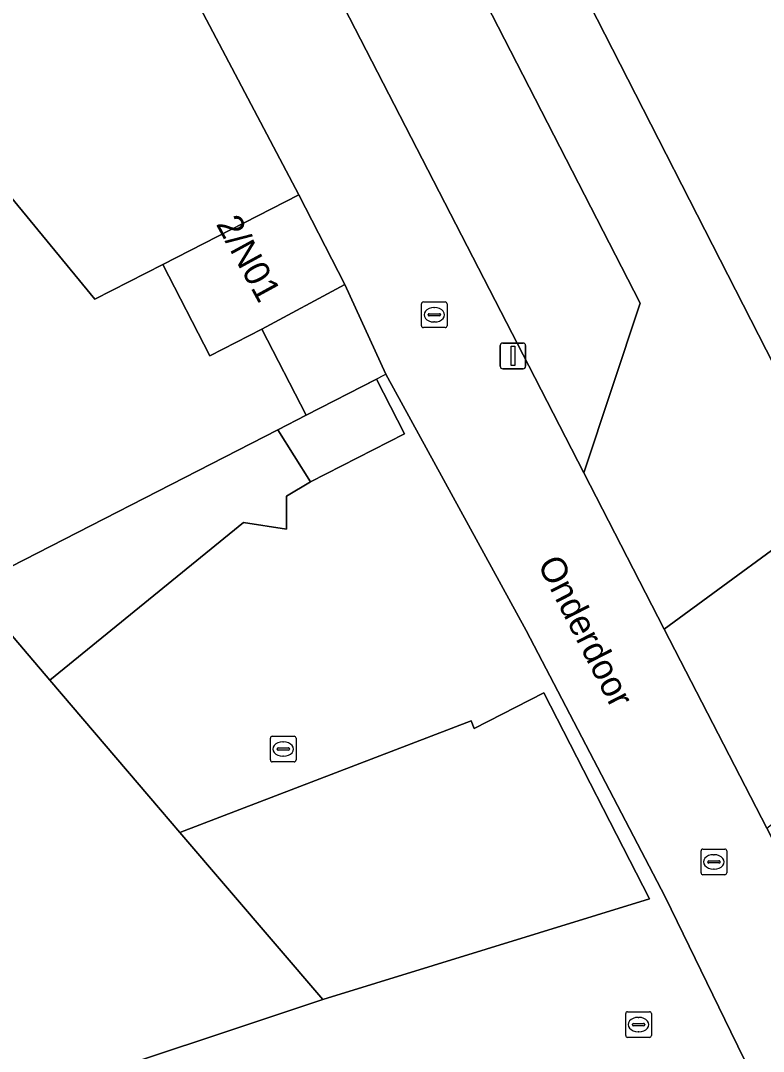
# Model space of a CAD drawing. Extents: x 161087 to 161926, y 382572 to 383873.
# Drawn here: x 161751.28 to 161780.24, y 382874.64 to 382914.81 of the extents above; entities that cross this region are included whole.
import ezdxf

# ---------------------------------------------------------------- set-up
doc = ezdxf.new("R2010")
doc.units = 0
for name, color, linetype in [('IMGEO_Erf', 7, 'Continuous'), ('IMGEO_Hek', 7, 'Continuous'), ('IMGEO_Kolk', 7, 'Continuous'), ('IMGEO_Lichtmast', 7, 'Continuous'), ('IMGEO_Muur', 7, 'Continuous'), ('IMGEO_Openbare_ruimte_label', 7, 'Continuous'), ('IMGEO_Pand', 7, 'Continuous'), ('IMGEO_Pand_nummerreeks', 7, 'Continuous'), ('IMGEO_Parkeervlak_gesloten', 7, 'Continuous'), ('IMGEO_Rijbaan_lokaal_gesloten', 7, 'Continuous'), ('IMGEO_Rijbaan_lokaal_open', 7, 'Continuous')]:
    doc.layers.add(name, color=color, linetype=linetype)

msp = doc.modelspace()

# ---------------------------------------------------------------- linework, layer by layer
at = {"layer": 'IMGEO_Erf'}
msp.add_lwpolyline([(161781.64, 382869.915), (161778.973, 382875.402), (161776.413, 382880.664), (161770.996, 382891.041), (161765.524, 382901.027), (161763.926, 382904.529), (161760.691, 382902.783), (161762.41, 382899.43), (161765.159, 382900.837), (161766.249, 382898.71), (161762.579, 382896.831), (161761.653, 382896.272), (161761.648, 382894.996), (161759.969, 382895.256), (161752.426, 382889.102), (161756.738, 382884.057), (161757.493, 382883.174), (161768.844, 382887.525), (161768.961, 382887.22), (161771.685, 382888.614), (161775.793, 382880.58), (161763.065, 382876.655), (161758.653, 382875.193), (161754.772, 382873.907)], dxfattribs=at)
at = {"layer": 'IMGEO_Hek'}
for points in [[(161771.091, 382901.359), (161773.236, 382897.192), (161776.376, 382891.093), (161780.366, 382883.342), (161784.138, 382876.015)], [(161762.41, 382899.43), (161765.524, 382901.027)], [(161765.524, 382901.027), (161770.996, 382891.041)]]:
    msp.add_lwpolyline(points, dxfattribs=at)
at = {"layer": 'IMGEO_Kolk'}
for p, q in [((161766.909, 382902.921), (161766.909, 382903.773)), ((161766.984, 382903.847), (161767.836, 382903.847)), ((161767.91, 382903.773), (161767.91, 382902.921)), ((161767.168, 382903.341), (161767.168, 382903.353)), ((161767.606, 382903.304), (161767.208, 382903.304)), ((161767.211, 382903.39), (161767.609, 382903.39)), ((161767.397, 382903.627), (161767.422, 382903.627)), ((161767.652, 382903.353), (161767.652, 382903.341)), ((161767.42, 382903.067), (161767.395, 382903.067)), ((161767.836, 382902.847), (161766.984, 382902.847)), ((161761.02, 382885.995), (161761.02, 382886.847)), ((161761.095, 382886.921), (161761.947, 382886.921)), ((161762.021, 382886.847), (161762.021, 382885.995)), ((161761.279, 382886.415), (161761.279, 382886.427)), ((161761.322, 382886.464), (161761.72, 382886.464)), ((161761.508, 382886.701), (161761.533, 382886.701)), ((161761.763, 382886.427), (161761.763, 382886.415)), ((161761.717, 382886.378), (161761.319, 382886.378)), ((161761.531, 382886.141), (161761.506, 382886.141)), ((161761.947, 382885.921), (161761.095, 382885.921)), ((161777.807, 382881.597), (161777.807, 382882.449)), ((161777.882, 382882.523), (161778.734, 382882.523)), ((161778.808, 382882.449), (161778.808, 382881.597)), ((161778.066, 382882.017), (161778.066, 382882.029)), ((161778.109, 382882.066), (161778.507, 382882.066)), ((161778.295, 382882.303), (161778.32, 382882.303)), ((161778.55, 382882.029), (161778.55, 382882.017)), ((161778.504, 382881.98), (161778.106, 382881.98)), ((161778.318, 382881.743), (161778.293, 382881.743)), ((161778.734, 382881.523), (161777.882, 382881.523)), ((161774.87, 382875.256), (161774.87, 382876.108)), ((161774.945, 382876.182), (161775.797, 382876.182)), ((161775.871, 382876.108), (161775.871, 382875.256)), ((161775.129, 382875.676), (161775.129, 382875.688)), ((161775.567, 382875.639), (161775.169, 382875.639)), ((161775.172, 382875.725), (161775.57, 382875.725)), ((161775.358, 382875.962), (161775.383, 382875.962)), ((161775.613, 382875.688), (161775.613, 382875.676)), ((161775.797, 382875.182), (161774.945, 382875.182)), ((161775.381, 382875.402), (161775.356, 382875.402))]:
    msp.add_line(p, q, dxfattribs=at)
for points in [[(161766.909, 382902.921), (161766.909, 382903.773)], [(161766.984, 382903.847), (161767.836, 382903.847)], [(161767.91, 382903.773), (161767.91, 382902.921)], [(161767.836, 382902.847), (161766.984, 382902.847)], [(161761.02, 382885.995), (161761.02, 382886.847)], [(161761.095, 382886.921), (161761.947, 382886.921)], [(161762.021, 382886.847), (161762.021, 382885.995)], [(161761.947, 382885.921), (161761.095, 382885.921)], [(161777.807, 382881.597), (161777.807, 382882.449)], [(161777.882, 382882.523), (161778.734, 382882.523)], [(161778.808, 382882.449), (161778.808, 382881.597)], [(161778.734, 382881.523), (161777.882, 382881.523)], [(161774.87, 382875.256), (161774.87, 382876.108)], [(161774.945, 382876.182), (161775.797, 382876.182)], [(161775.871, 382876.108), (161775.871, 382875.256)], [(161775.797, 382875.182), (161774.945, 382875.182)]]:
    msp.add_lwpolyline(points, dxfattribs=at)
for centre, radius, start, end in [((161766.986, 382903.771), 0.0765, 91.552, 178.448), ((161766.986, 382903.771), 0.0765, 91.552, 178.448), ((161767.834, 382903.771), 0.0765, 1.552, 88.448), ((161767.834, 382903.771), 0.0765, 1.552, 88.448), ((161767.208, 382903.35), 0.0403, 85.8775, 175.7526), ((161767.205, 382903.34), 0.0366, 178.938, 274.7102), ((161767.609, 382903.347), 0.043, 264.8664, 352.4533), ((161767.613, 382903.352), 0.0386, 1.7309, 96.639), ((161766.986, 382902.923), 0.0765, 181.552, 268.448), ((161766.986, 382902.923), 0.0765, 181.552, 268.448), ((161767.834, 382902.923), 0.0765, 271.552, 358.448), ((161767.834, 382902.923), 0.0765, 271.552, 358.448), ((161761.097, 382886.845), 0.0765, 91.552, 178.448), ((161761.097, 382886.845), 0.0765, 91.552, 178.448), ((161761.945, 382886.845), 0.0765, 1.552, 88.448), ((161761.945, 382886.845), 0.0765, 1.552, 88.448), ((161761.319, 382886.424), 0.0403, 85.8775, 175.7526), ((161761.724, 382886.426), 0.0386, 1.7309, 96.639), ((161761.316, 382886.414), 0.0366, 178.938, 274.7102), ((161761.72, 382886.421), 0.043, 264.8664, 352.4533), ((161761.097, 382885.997), 0.0765, 181.552, 268.448), ((161761.097, 382885.997), 0.0765, 181.552, 268.448), ((161761.945, 382885.997), 0.0765, 271.552, 358.448), ((161761.945, 382885.997), 0.0765, 271.552, 358.448), ((161777.884, 382882.447), 0.0765, 91.552, 178.448), ((161777.884, 382882.447), 0.0765, 91.552, 178.448), ((161778.732, 382882.447), 0.0765, 1.552, 88.448), ((161778.732, 382882.447), 0.0765, 1.552, 88.448), ((161778.106, 382882.026), 0.0403, 85.8775, 175.7526), ((161778.103, 382882.016), 0.0366, 178.938, 274.7102), ((161778.507, 382882.023), 0.043, 264.8664, 352.4533), ((161778.511, 382882.028), 0.0386, 1.7309, 96.639), ((161777.884, 382881.599), 0.0765, 181.552, 268.448), ((161777.884, 382881.599), 0.0765, 181.552, 268.448), ((161778.732, 382881.599), 0.0765, 271.552, 358.448), ((161778.732, 382881.599), 0.0765, 271.552, 358.448), ((161774.947, 382876.106), 0.0765, 91.552, 178.448), ((161774.947, 382876.106), 0.0765, 91.552, 178.448), ((161775.795, 382876.106), 0.0765, 1.552, 88.448), ((161775.795, 382876.106), 0.0765, 1.552, 88.448), ((161775.169, 382875.685), 0.0403, 85.8775, 175.7526), ((161775.166, 382875.675), 0.0366, 178.938, 274.7102), ((161775.57, 382875.682), 0.043, 264.8664, 352.4533), ((161775.574, 382875.687), 0.0386, 1.7309, 96.639), ((161774.947, 382875.258), 0.0765, 181.552, 268.448), ((161774.947, 382875.258), 0.0765, 181.552, 268.448), ((161775.795, 382875.258), 0.0765, 271.552, 358.448), ((161775.795, 382875.258), 0.0765, 271.552, 358.448)]:
    msp.add_arc(centre, radius, start, end, dxfattribs=at)
for centre, major_axis, ratio, start_param, end_param in [((161767.396, 382903.347), (-0.387, 0.002), 0.722429, 4.712389, 7.853982), ((161767.421, 382903.347), (-0.39, 0.002), 0.717154, 1.570796, 4.712389), ((161761.507, 382886.421), (-0.387, 0.002), 0.722429, 4.712389, 7.853982), ((161761.532, 382886.421), (-0.39, 0.002), 0.717154, 1.570796, 4.712389), ((161778.294, 382882.023), (-0.387, 0.002), 0.722429, 4.712389, 7.853982), ((161778.319, 382882.023), (-0.39, 0.002), 0.717154, 1.570796, 4.712389), ((161775.357, 382875.682), (-0.387, 0.002), 0.722429, 4.712389, 7.853982), ((161775.382, 382875.682), (-0.39, 0.002), 0.717154, 1.570796, 4.712389)]:
    msp.add_ellipse(centre, major_axis=major_axis, ratio=ratio, start_param=start_param, end_param=end_param, dxfattribs=at)
at = {"layer": 'IMGEO_Lichtmast'}
for p, q in [((161769.98, 382901.344), (161769.98, 382902.144)), ((161769.98, 382902.144), (161769.98, 382901.344)), ((161770.08, 382902.244), (161770.87, 382902.244)), ((161770.87, 382902.244), (161770.08, 382902.244)), ((161770.97, 382902.144), (161770.97, 382901.344)), ((161770.97, 382901.344), (161770.97, 382902.144)), ((161770.87, 382901.244), (161770.08, 382901.244)), ((161770.08, 382901.244), (161770.87, 382901.244))]:
    msp.add_line(p, q, dxfattribs=at)
msp.add_lwpolyline([(161770.4, 382902.119), (161770.55, 382902.119), (161770.55, 382901.369), (161770.4, 382901.369), (161770.4, 382902.119)], dxfattribs=at)
for centre, start, end in [((161770.08, 382902.144), 90, 180), ((161770.08, 382902.144), 90, 180), ((161770.87, 382902.144), 0, 90), ((161770.87, 382902.144), 360, 90), ((161770.08, 382901.344), 180, 270), ((161770.08, 382901.344), 180, 270), ((161770.87, 382901.344), 270, 0), ((161770.87, 382901.344), 270, 0)]:
    msp.add_arc(centre, 0.1, start, end, dxfattribs=at)
at = {"layer": 'IMGEO_Muur'}
msp.add_lwpolyline([(161771.091, 382901.359), (161759.078, 382924.694), (161758.477, 382925.861), (161758.374, 382926.061)], dxfattribs=at)
at = {"layer": 'IMGEO_Pand'}
for points in [[(161754.557, 382922.389), (161753.84, 382922.8), (161753.782, 382922.714), (161750.898, 382924.454), (161747.568, 382926.463), (161745.707, 382923.342), (161744.597, 382921.593), (161743.601, 382920.025), (161744.97, 382918.413), (161744.477, 382918.008), (161743.372, 382917.1), (161754.178, 382903.953), (161756.831, 382905.311), (161762.135, 382908.027)], [(161743.372, 382917.1), (161742.833, 382917.756), (161734.176, 382910.454), (161749.325, 382892.73), (161761.314, 382898.869), (161762.41, 382899.43), (161760.691, 382902.783), (161758.659, 382901.742), (161756.831, 382905.311), (161754.178, 382903.953)], [(161756.831, 382905.311), (161758.659, 382901.742), (161760.691, 382902.783), (161763.926, 382904.529), (161762.135, 382908.027)], [(161762.41, 382899.43), (161761.314, 382898.869), (161762.579, 382896.831), (161766.249, 382898.71), (161765.159, 382900.837)], [(161761.653, 382896.272), (161762.579, 382896.831), (161761.314, 382898.869), (161749.325, 382892.73), (161752.426, 382889.102), (161759.969, 382895.256), (161761.648, 382894.996)], [(161757.493, 382883.174), (161756.738, 382884.057), (161752.426, 382889.102), (161749.325, 382892.73), (161738.945, 382887.9), (161749.174, 382875.709), (161751.118, 382873.436), (161751.61, 382872.86), (161754.772, 382873.907), (161758.653, 382875.193), (161763.065, 382876.655)], [(161771.685, 382888.614), (161768.961, 382887.22), (161768.844, 382887.525), (161757.493, 382883.174), (161763.065, 382876.655), (161775.793, 382880.58)]]:
    msp.add_lwpolyline(points, close=True, dxfattribs=at)
at = {"layer": 'IMGEO_Parkeervlak_gesloten'}
for points in [[(161756.155, 382941.205), (161754.545, 382938.531), (161751.449, 382933.387), (161756.058, 382930.699), (161758.374, 382926.061), (161758.477, 382925.861), (161759.078, 382924.694), (161771.091, 382901.359), (161773.236, 382897.192), (161775.431, 382903.801), (161761, 382931.897)], [(161787.763, 382889.132), (161785.452, 382892.043), (161783.036, 382895.982), (161776.376, 382891.093), (161780.366, 382883.342)]]:
    msp.add_lwpolyline(points, close=True, dxfattribs=at)
msp.add_lwpolyline([(161765.074, 382931.859), (161780.649, 382901.401)], dxfattribs=at)
at = {"layer": 'IMGEO_Rijbaan_lokaal_gesloten'}
msp.add_lwpolyline([(161770.001, 382940.906), (161768.956, 382940.174), (161767.325, 382942.503), (161772.375, 382946.039), (161770.116, 382949.117), (161765.214, 382952.918), (161763.844, 382953.981), (161760.245, 382948), (161757.765, 382943.88), (161756.155, 382941.205), (161761, 382931.897), (161775.431, 382903.801), (161773.236, 382897.192), (161776.376, 382891.093), (161783.036, 382895.982), (161785.452, 382892.043), (161787.763, 382889.132), (161792.612, 382883.021), (161794.956, 382884.96), (161790.275, 382890.622), (161787.541, 382893.928), (161798.678, 382902.905), (161790.437, 382913.051)], close=True, dxfattribs=at)
msp.add_lwpolyline([(161780.649, 382901.401), (161765.074, 382931.859)], dxfattribs=at)
at = {"layer": 'IMGEO_Rijbaan_lokaal_open'}
msp.add_lwpolyline([(161789.672, 382865.069), (161784.138, 382876.015), (161780.366, 382883.342), (161776.376, 382891.093), (161773.236, 382897.192), (161771.091, 382901.359), (161759.078, 382924.694), (161754.557, 382922.389), (161762.135, 382908.027), (161763.926, 382904.529), (161765.524, 382901.027), (161770.996, 382891.041), (161776.413, 382880.664), (161778.973, 382875.402), (161781.64, 382869.915)], dxfattribs=at)

# ---------------------------------------------------------------- texts
at = {"layer": 'IMGEO_Openbare_ruimte_label'}
msp.add_text('Onderdoor', height=1, rotation=297.1288, dxfattribs=at).set_placement((161771.417, 382893.635))
at = {"layer": 'IMGEO_Pand_nummerreeks'}
msp.add_text('2/N01', height=1, rotation=298.6105, dxfattribs=at).set_placement((161758.883, 382906.884))

doc.saveas('drawing.dxf')
